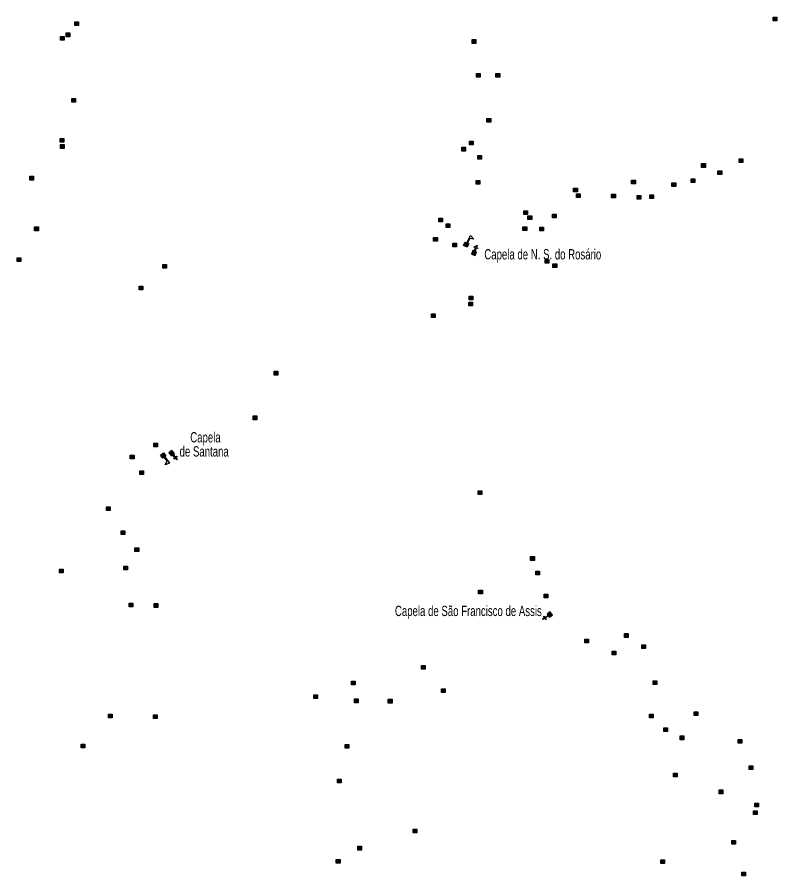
# Model space of a CAD drawing. Extents: x 649.2 to 674.4, y 7040 to 7068.1.
# Drawn here: x 662.26 to 668.19, y 7047.06 to 7053.75 of the extents above; entities that cross this region are included whole.
import ezdxf
from ezdxf.enums import TextEntityAlignment as Align

# ---------------------------------------------------------------- set-up
doc = ezdxf.new("R2010")
doc.units = 0
doc.header["$LTSCALE"] = 0.032
for name, color, linetype, lineweight in [('2', 7, 'Continuous', 25), ('4', 7, 'Continuous', 25), ('6', 7, 'Continuous', 25)]:
    doc.layers.add(name, color=color, linetype=linetype, lineweight=lineweight)
doc.layers.add('61', color=7, linetype='Continuous')

msp = doc.modelspace()

# ---------------------------------------------------------------- hatches: boundary and pattern name
at = {"layer": '2'}
for points in [[(668.1563, 7053.7499), (668.1853, 7053.7499), (668.1853, 7053.7209), (668.1563, 7053.7209)], [(662.7131, 7053.714), (662.7421, 7053.714), (662.7421, 7053.685), (662.7131, 7053.685)], [(662.6028, 7053.5993), (662.6318, 7053.5993), (662.6318, 7053.5703), (662.6028, 7053.5703)], [(662.645, 7053.6269), (662.674, 7053.6269), (662.674, 7053.5979), (662.645, 7053.5979)], [(665.811, 7053.5749), (665.84, 7053.5749), (665.84, 7053.5459), (665.811, 7053.5459)], [(665.8449, 7053.3102), (665.8739, 7053.3102), (665.8739, 7053.2812), (665.8449, 7053.2812)], [(665.9962, 7053.3115), (666.0252, 7053.3115), (666.0252, 7053.2825), (665.9962, 7053.2825)], [(662.6896, 7053.1161), (662.7186, 7053.1161), (662.7186, 7053.0871), (662.6896, 7053.0871)], [(665.9261, 7052.9598), (665.9551, 7052.9598), (665.9551, 7052.9308), (665.9261, 7052.9308)], [(662.5997, 7052.8044), (662.6287, 7052.8044), (662.6287, 7052.7754), (662.5997, 7052.7754)], [(662.6025, 7052.7567), (662.6315, 7052.7567), (662.6315, 7052.7277), (662.6025, 7052.7277)], [(665.7295, 7052.7358), (665.7585, 7052.7358), (665.7585, 7052.7068), (665.7295, 7052.7068)], [(665.7906, 7052.7828), (665.8196, 7052.7828), (665.8196, 7052.7538), (665.7906, 7052.7538)], [(665.8556, 7052.6727), (665.8846, 7052.6727), (665.8846, 7052.6437), (665.8556, 7052.6437)], [(667.5991, 7052.6086), (667.6281, 7052.6086), (667.6281, 7052.5796), (667.5991, 7052.5796)], [(667.8915, 7052.6472), (667.9205, 7052.6472), (667.9205, 7052.6182), (667.8915, 7052.6182)], [(667.7264, 7052.5524), (667.7554, 7052.5524), (667.7554, 7052.5234), (667.7264, 7052.5234)], [(662.3625, 7052.5097), (662.3915, 7052.5097), (662.3915, 7052.4807), (662.3625, 7052.4807)], [(665.8415, 7052.4779), (665.8705, 7052.4779), (665.8705, 7052.4489), (665.8415, 7052.4489)], [(667.0535, 7052.4799), (667.0825, 7052.4799), (667.0825, 7052.4509), (667.0535, 7052.4509)], [(667.3682, 7052.4585), (667.3972, 7052.4585), (667.3972, 7052.4295), (667.3682, 7052.4295)], [(667.5183, 7052.4909), (667.5473, 7052.4909), (667.5473, 7052.4619), (667.5183, 7052.4619)], [(666.6017, 7052.4172), (666.6307, 7052.4172), (666.6307, 7052.3882), (666.6017, 7052.3882)], [(666.6241, 7052.3725), (666.6531, 7052.3725), (666.6531, 7052.3435), (666.6241, 7052.3435)], [(666.8979, 7052.3717), (666.9269, 7052.3717), (666.9269, 7052.3427), (666.8979, 7052.3427)], [(667.0967, 7052.3615), (667.1257, 7052.3615), (667.1257, 7052.3325), (667.0967, 7052.3325)], [(667.1946, 7052.3651), (667.2236, 7052.3651), (667.2236, 7052.3361), (667.1946, 7052.3361)], [(666.2126, 7052.2412), (666.2416, 7052.2412), (666.2416, 7052.2122), (666.2126, 7052.2122)], [(666.2457, 7052.2023), (666.2747, 7052.2023), (666.2747, 7052.1733), (666.2457, 7052.1733)], [(666.4363, 7052.2149), (666.4653, 7052.2149), (666.4653, 7052.1859), (666.4363, 7052.1859)], [(665.5504, 7052.1842), (665.5794, 7052.1842), (665.5794, 7052.1552), (665.5504, 7052.1552)], [(665.6087, 7052.1395), (665.6377, 7052.1395), (665.6377, 7052.1105), (665.6087, 7052.1105)], [(662.4005, 7052.1151), (662.4295, 7052.1151), (662.4295, 7052.0861), (662.4005, 7052.0861)], [(666.2068, 7052.1157), (666.2358, 7052.1157), (666.2358, 7052.0867), (666.2068, 7052.0867)], [(666.3381, 7052.1147), (666.3671, 7052.1147), (666.3671, 7052.0857), (666.3381, 7052.0857)], [(665.5104, 7052.0332), (665.5394, 7052.0332), (665.5394, 7052.0042), (665.5104, 7052.0042)], [(665.6591, 7051.9884), (665.6881, 7051.9884), (665.6881, 7051.9594), (665.6591, 7051.9594)], [(662.2642, 7051.8752), (662.2932, 7051.8752), (662.2932, 7051.8462), (662.2642, 7051.8462)], [(666.3798, 7051.8613), (666.4088, 7051.8613), (666.4088, 7051.8323), (666.3798, 7051.8323)], [(663.3997, 7051.8231), (663.4287, 7051.8231), (663.4287, 7051.7941), (663.3997, 7051.7941)], [(666.4403, 7051.829), (666.4693, 7051.829), (666.4693, 7051.8), (666.4403, 7051.8)], [(663.2147, 7051.6548), (663.2437, 7051.6548), (663.2437, 7051.6258), (663.2147, 7051.6258)], [(665.7852, 7051.5282), (665.8142, 7051.5282), (665.8142, 7051.4992), (665.7852, 7051.4992)], [(665.7871, 7051.5751), (665.8161, 7051.5751), (665.8161, 7051.5461), (665.7871, 7051.5461)], [(665.4924, 7051.4392), (665.5214, 7051.4392), (665.5214, 7051.4102), (665.4924, 7051.4102)], [(664.267, 7050.9904), (664.296, 7050.9904), (664.296, 7050.9614), (664.267, 7050.9614)], [(664.1026, 7050.6421), (664.1316, 7050.6421), (664.1316, 7050.6131), (664.1026, 7050.6131)], [(663.3297, 7050.431), (663.3587, 7050.431), (663.3587, 7050.402), (663.3297, 7050.402)], [(663.146, 7050.3366), (663.175, 7050.3366), (663.175, 7050.3076), (663.146, 7050.3076)], [(663.2206, 7050.2153), (663.2496, 7050.2153), (663.2496, 7050.1863), (663.2206, 7050.1863)], [(665.8575, 7050.0582), (665.8865, 7050.0582), (665.8865, 7050.0292), (665.8575, 7050.0292)], [(662.9598, 7049.9353), (662.9888, 7049.9353), (662.9888, 7049.9063), (662.9598, 7049.9063)], [(663.0741, 7049.7483), (663.1031, 7049.7483), (663.1031, 7049.7193), (663.0741, 7049.7193)], [(663.1824, 7049.6147), (663.2114, 7049.6147), (663.2114, 7049.5857), (663.1824, 7049.5857)], [(666.2664, 7049.5462), (666.2954, 7049.5462), (666.2954, 7049.5172), (666.2664, 7049.5172)], [(662.5947, 7049.4484), (662.6237, 7049.4484), (662.6237, 7049.4194), (662.5947, 7049.4194)], [(663.0949, 7049.4722), (663.1239, 7049.4722), (663.1239, 7049.4432), (663.0949, 7049.4432)], [(666.3071, 7049.4324), (666.3361, 7049.4324), (666.3361, 7049.4034), (666.3071, 7049.4034)], [(665.861, 7049.286), (665.89, 7049.286), (665.89, 7049.257), (665.861, 7049.257)], [(666.3711, 7049.2535), (666.4001, 7049.2535), (666.4001, 7049.2245), (666.3711, 7049.2245)], [(663.1364, 7049.1828), (663.1654, 7049.1828), (663.1654, 7049.1538), (663.1364, 7049.1538)], [(663.3324, 7049.1798), (663.3614, 7049.1798), (663.3614, 7049.1508), (663.3324, 7049.1508)], [(666.9973, 7048.946), (667.0263, 7048.946), (667.0263, 7048.917), (666.9973, 7048.917)], [(666.6883, 7048.9031), (666.7173, 7048.9031), (666.7173, 7048.8741), (666.6883, 7048.8741)], [(667.1336, 7048.8593), (667.1626, 7048.8593), (667.1626, 7048.8303), (667.1336, 7048.8303)], [(666.9023, 7048.8097), (666.9313, 7048.8097), (666.9313, 7048.7807), (666.9023, 7048.7807)], [(665.4155, 7048.6974), (665.4445, 7048.6974), (665.4445, 7048.6684), (665.4155, 7048.6684)], [(667.2212, 7048.5782), (667.2502, 7048.5782), (667.2502, 7048.5492), (667.2212, 7048.5492)], [(664.869, 7048.5753), (664.898, 7048.5753), (664.898, 7048.5463), (664.869, 7048.5463)], [(665.5709, 7048.5156), (665.5999, 7048.5156), (665.5999, 7048.4866), (665.5709, 7048.4866)], [(664.5755, 7048.4699), (664.6045, 7048.4699), (664.6045, 7048.4409), (664.5755, 7048.4409)], [(664.8937, 7048.437), (664.9227, 7048.437), (664.9227, 7048.408), (664.8937, 7048.408)], [(665.157, 7048.4341), (665.186, 7048.4341), (665.186, 7048.4051), (665.157, 7048.4051)], [(662.9751, 7048.319), (663.0041, 7048.319), (663.0041, 7048.29), (662.9751, 7048.29)], [(663.3259, 7048.3145), (663.3549, 7048.3145), (663.3549, 7048.2855), (663.3259, 7048.2855)], [(667.1921, 7048.319), (667.2211, 7048.319), (667.2211, 7048.29), (667.1921, 7048.29)], [(667.5412, 7048.3375), (667.5702, 7048.3375), (667.5702, 7048.3085), (667.5412, 7048.3085)], [(667.3045, 7048.2132), (667.3335, 7048.2132), (667.3335, 7048.1842), (667.3045, 7048.1842)], [(667.4314, 7048.1484), (667.4604, 7048.1484), (667.4604, 7048.1194), (667.4314, 7048.1194)], [(667.8838, 7048.1206), (667.9128, 7048.1206), (667.9128, 7048.0916), (667.8838, 7048.0916)], [(662.7631, 7048.0845), (662.7921, 7048.0845), (662.7921, 7048.0555), (662.7631, 7048.0555)], [(664.8205, 7048.0823), (664.8495, 7048.0823), (664.8495, 7048.0533), (664.8205, 7048.0533)], [(667.9692, 7047.9162), (667.9982, 7047.9162), (667.9982, 7047.8872), (667.9692, 7047.8872)], [(667.3801, 7047.8582), (667.4091, 7047.8582), (667.4091, 7047.8292), (667.3801, 7047.8292)], [(664.7604, 7047.8114), (664.7894, 7047.8114), (664.7894, 7047.7824), (664.7604, 7047.7824)], [(667.735, 7047.7279), (667.764, 7047.7279), (667.764, 7047.6989), (667.735, 7047.6989)], [(668.0138, 7047.6241), (668.0428, 7047.6241), (668.0428, 7047.5951), (668.0138, 7047.5951)], [(668.0042, 7047.5649), (668.0332, 7047.5649), (668.0332, 7047.5359), (668.0042, 7047.5359)], [(665.3506, 7047.4223), (665.3796, 7047.4223), (665.3796, 7047.3933), (665.3506, 7047.3933)], [(667.8344, 7047.335), (667.8634, 7047.335), (667.8634, 7047.306), (667.8344, 7047.306)], [(664.9203, 7047.2888), (664.9493, 7047.2888), (664.9493, 7047.2598), (664.9203, 7047.2598)], [(664.7517, 7047.1857), (664.7807, 7047.1857), (664.7807, 7047.1567), (664.7517, 7047.1567)], [(667.2809, 7047.1826), (667.3099, 7047.1826), (667.3099, 7047.1536), (667.2809, 7047.1536)], [(667.9123, 7047.0877), (667.9413, 7047.0877), (667.9413, 7047.0587), (667.9123, 7047.0587)]]:
    msp.add_hatch(color=256, dxfattribs=at).paths.add_polyline_path(points)
at = {"layer": '4'}
for points in [[(665.7441, 7051.9711), (665.7578, 7051.9977), (665.7845, 7051.984), (665.7708, 7051.9573)], [(663.4059, 7050.3545), (663.4242, 7050.3308), (663.4004, 7050.3125), (663.3821, 7050.3362)]]:
    msp.add_hatch(color=256, dxfattribs=at).paths.add_polyline_path(points)
at = {"layer": '6'}
for points in [[(665.8158, 7051.9312), (665.8051, 7051.9032), (665.8331, 7051.8925), (665.8438, 7051.9205)], [(665.8321, 7051.925), (665.8275, 7051.9267), (665.8373, 7051.9524), (665.8256, 7051.9569), (665.8273, 7051.9616), (665.839, 7051.9571), (665.8453, 7051.9735), (665.8499, 7051.9717), (665.8437, 7051.9553), (665.8554, 7051.9509), (665.8536, 7051.9462), (665.8419, 7051.9507)], [(663.4893, 7050.3505), (663.47, 7050.3734), (663.4471, 7050.354), (663.4664, 7050.3311)], [(663.476, 7050.3392), (663.4798, 7050.3424), (663.4975, 7050.3214), (663.5071, 7050.3295), (663.5103, 7050.3256), (663.5007, 7050.3176), (663.512, 7050.3042), (663.5082, 7050.301), (663.4969, 7050.3143), (663.4874, 7050.3063), (663.4841, 7050.3101), (663.4937, 7050.3182)], [(666.4112, 7049.074), (666.4359, 7049.0909), (666.4191, 7049.1157), (666.3943, 7049.0988)], [(666.4013, 7049.0885), (666.4041, 7049.0843), (666.3814, 7049.0688), (666.3884, 7049.0585), (666.3843, 7049.0557), (666.3773, 7049.066), (666.3628, 7049.0562), (666.36, 7049.0603), (666.3744, 7049.0702), (666.3674, 7049.0805), (666.3715, 7049.0833), (666.3786, 7049.073)]]:
    msp.add_hatch(color=256, dxfattribs=at).paths.add_polyline_path(points)

# ---------------------------------------------------------------- linework, layer by layer
at = {"layer": '2'}
for points in [[(668.1563, 7053.7499), (668.1853, 7053.7499), (668.1853, 7053.7209), (668.1563, 7053.7209)], [(662.7131, 7053.714), (662.7421, 7053.714), (662.7421, 7053.685), (662.7131, 7053.685)], [(662.6028, 7053.5993), (662.6318, 7053.5993), (662.6318, 7053.5703), (662.6028, 7053.5703)], [(662.645, 7053.6269), (662.674, 7053.6269), (662.674, 7053.5979), (662.645, 7053.5979)], [(665.811, 7053.5749), (665.84, 7053.5749), (665.84, 7053.5459), (665.811, 7053.5459)], [(665.8449, 7053.3102), (665.8739, 7053.3102), (665.8739, 7053.2812), (665.8449, 7053.2812)], [(665.9962, 7053.3115), (666.0252, 7053.3115), (666.0252, 7053.2825), (665.9962, 7053.2825)], [(662.6896, 7053.1161), (662.7186, 7053.1161), (662.7186, 7053.0871), (662.6896, 7053.0871)], [(665.9261, 7052.9598), (665.9551, 7052.9598), (665.9551, 7052.9308), (665.9261, 7052.9308)], [(662.5997, 7052.8044), (662.6287, 7052.8044), (662.6287, 7052.7754), (662.5997, 7052.7754)], [(662.6025, 7052.7567), (662.6315, 7052.7567), (662.6315, 7052.7277), (662.6025, 7052.7277)], [(665.7295, 7052.7358), (665.7585, 7052.7358), (665.7585, 7052.7068), (665.7295, 7052.7068)], [(665.7906, 7052.7828), (665.8196, 7052.7828), (665.8196, 7052.7538), (665.7906, 7052.7538)], [(665.8556, 7052.6727), (665.8846, 7052.6727), (665.8846, 7052.6437), (665.8556, 7052.6437)], [(667.5991, 7052.6086), (667.6281, 7052.6086), (667.6281, 7052.5796), (667.5991, 7052.5796)], [(667.8915, 7052.6472), (667.9205, 7052.6472), (667.9205, 7052.6182), (667.8915, 7052.6182)], [(667.7264, 7052.5524), (667.7554, 7052.5524), (667.7554, 7052.5234), (667.7264, 7052.5234)], [(662.3625, 7052.5097), (662.3915, 7052.5097), (662.3915, 7052.4807), (662.3625, 7052.4807)], [(665.8415, 7052.4779), (665.8705, 7052.4779), (665.8705, 7052.4489), (665.8415, 7052.4489)], [(667.0535, 7052.4799), (667.0825, 7052.4799), (667.0825, 7052.4509), (667.0535, 7052.4509)], [(667.3682, 7052.4585), (667.3972, 7052.4585), (667.3972, 7052.4295), (667.3682, 7052.4295)], [(667.5183, 7052.4909), (667.5473, 7052.4909), (667.5473, 7052.4619), (667.5183, 7052.4619)], [(666.6017, 7052.4172), (666.6307, 7052.4172), (666.6307, 7052.3882), (666.6017, 7052.3882)], [(666.6241, 7052.3725), (666.6531, 7052.3725), (666.6531, 7052.3435), (666.6241, 7052.3435)], [(666.8979, 7052.3717), (666.9269, 7052.3717), (666.9269, 7052.3427), (666.8979, 7052.3427)], [(667.0967, 7052.3615), (667.1257, 7052.3615), (667.1257, 7052.3325), (667.0967, 7052.3325)], [(667.1946, 7052.3651), (667.2236, 7052.3651), (667.2236, 7052.3361), (667.1946, 7052.3361)], [(666.2126, 7052.2412), (666.2416, 7052.2412), (666.2416, 7052.2122), (666.2126, 7052.2122)], [(666.2457, 7052.2023), (666.2747, 7052.2023), (666.2747, 7052.1733), (666.2457, 7052.1733)], [(666.4363, 7052.2149), (666.4653, 7052.2149), (666.4653, 7052.1859), (666.4363, 7052.1859)], [(665.5504, 7052.1842), (665.5794, 7052.1842), (665.5794, 7052.1552), (665.5504, 7052.1552)], [(665.6087, 7052.1395), (665.6377, 7052.1395), (665.6377, 7052.1105), (665.6087, 7052.1105)], [(662.4005, 7052.1151), (662.4295, 7052.1151), (662.4295, 7052.0861), (662.4005, 7052.0861)], [(666.2068, 7052.1157), (666.2358, 7052.1157), (666.2358, 7052.0867), (666.2068, 7052.0867)], [(666.3381, 7052.1147), (666.3671, 7052.1147), (666.3671, 7052.0857), (666.3381, 7052.0857)], [(665.5104, 7052.0332), (665.5394, 7052.0332), (665.5394, 7052.0042), (665.5104, 7052.0042)], [(665.6591, 7051.9884), (665.6881, 7051.9884), (665.6881, 7051.9594), (665.6591, 7051.9594)], [(662.2642, 7051.8752), (662.2932, 7051.8752), (662.2932, 7051.8462), (662.2642, 7051.8462)], [(666.3798, 7051.8613), (666.4088, 7051.8613), (666.4088, 7051.8323), (666.3798, 7051.8323)], [(663.3997, 7051.8231), (663.4287, 7051.8231), (663.4287, 7051.7941), (663.3997, 7051.7941)], [(666.4403, 7051.829), (666.4693, 7051.829), (666.4693, 7051.8), (666.4403, 7051.8)], [(663.2147, 7051.6548), (663.2437, 7051.6548), (663.2437, 7051.6258), (663.2147, 7051.6258)], [(665.7852, 7051.5282), (665.8142, 7051.5282), (665.8142, 7051.4992), (665.7852, 7051.4992)], [(665.7871, 7051.5751), (665.8161, 7051.5751), (665.8161, 7051.5461), (665.7871, 7051.5461)], [(665.4924, 7051.4392), (665.5214, 7051.4392), (665.5214, 7051.4102), (665.4924, 7051.4102)], [(664.267, 7050.9904), (664.296, 7050.9904), (664.296, 7050.9614), (664.267, 7050.9614)], [(664.1026, 7050.6421), (664.1316, 7050.6421), (664.1316, 7050.6131), (664.1026, 7050.6131)], [(663.3297, 7050.431), (663.3587, 7050.431), (663.3587, 7050.402), (663.3297, 7050.402)], [(663.146, 7050.3366), (663.175, 7050.3366), (663.175, 7050.3076), (663.146, 7050.3076)], [(663.2206, 7050.2153), (663.2496, 7050.2153), (663.2496, 7050.1863), (663.2206, 7050.1863)], [(665.8575, 7050.0582), (665.8865, 7050.0582), (665.8865, 7050.0292), (665.8575, 7050.0292)], [(662.9598, 7049.9353), (662.9888, 7049.9353), (662.9888, 7049.9063), (662.9598, 7049.9063)], [(663.0741, 7049.7483), (663.1031, 7049.7483), (663.1031, 7049.7193), (663.0741, 7049.7193)], [(663.1824, 7049.6147), (663.2114, 7049.6147), (663.2114, 7049.5857), (663.1824, 7049.5857)], [(666.2664, 7049.5462), (666.2954, 7049.5462), (666.2954, 7049.5172), (666.2664, 7049.5172)], [(662.5947, 7049.4484), (662.6237, 7049.4484), (662.6237, 7049.4194), (662.5947, 7049.4194)], [(663.0949, 7049.4722), (663.1239, 7049.4722), (663.1239, 7049.4432), (663.0949, 7049.4432)], [(666.3071, 7049.4324), (666.3361, 7049.4324), (666.3361, 7049.4034), (666.3071, 7049.4034)], [(665.861, 7049.286), (665.89, 7049.286), (665.89, 7049.257), (665.861, 7049.257)], [(666.3711, 7049.2535), (666.4001, 7049.2535), (666.4001, 7049.2245), (666.3711, 7049.2245)], [(663.1364, 7049.1828), (663.1654, 7049.1828), (663.1654, 7049.1538), (663.1364, 7049.1538)], [(663.3324, 7049.1798), (663.3614, 7049.1798), (663.3614, 7049.1508), (663.3324, 7049.1508)], [(666.9973, 7048.946), (667.0263, 7048.946), (667.0263, 7048.917), (666.9973, 7048.917)], [(666.6883, 7048.9031), (666.7173, 7048.9031), (666.7173, 7048.8741), (666.6883, 7048.8741)], [(667.1336, 7048.8593), (667.1626, 7048.8593), (667.1626, 7048.8303), (667.1336, 7048.8303)], [(666.9023, 7048.8097), (666.9313, 7048.8097), (666.9313, 7048.7807), (666.9023, 7048.7807)], [(665.4155, 7048.6974), (665.4445, 7048.6974), (665.4445, 7048.6684), (665.4155, 7048.6684)], [(667.2212, 7048.5782), (667.2502, 7048.5782), (667.2502, 7048.5492), (667.2212, 7048.5492)], [(664.869, 7048.5753), (664.898, 7048.5753), (664.898, 7048.5463), (664.869, 7048.5463)], [(665.5709, 7048.5156), (665.5999, 7048.5156), (665.5999, 7048.4866), (665.5709, 7048.4866)], [(664.5755, 7048.4699), (664.6045, 7048.4699), (664.6045, 7048.4409), (664.5755, 7048.4409)], [(664.8937, 7048.437), (664.9227, 7048.437), (664.9227, 7048.408), (664.8937, 7048.408)], [(665.157, 7048.4341), (665.186, 7048.4341), (665.186, 7048.4051), (665.157, 7048.4051)], [(662.9751, 7048.319), (663.0041, 7048.319), (663.0041, 7048.29), (662.9751, 7048.29)], [(663.3259, 7048.3145), (663.3549, 7048.3145), (663.3549, 7048.2855), (663.3259, 7048.2855)], [(667.1921, 7048.319), (667.2211, 7048.319), (667.2211, 7048.29), (667.1921, 7048.29)], [(667.5412, 7048.3375), (667.5702, 7048.3375), (667.5702, 7048.3085), (667.5412, 7048.3085)], [(667.3045, 7048.2132), (667.3335, 7048.2132), (667.3335, 7048.1842), (667.3045, 7048.1842)], [(667.4314, 7048.1484), (667.4604, 7048.1484), (667.4604, 7048.1194), (667.4314, 7048.1194)], [(667.8838, 7048.1206), (667.9128, 7048.1206), (667.9128, 7048.0916), (667.8838, 7048.0916)], [(662.7631, 7048.0845), (662.7921, 7048.0845), (662.7921, 7048.0555), (662.7631, 7048.0555)], [(664.8205, 7048.0823), (664.8495, 7048.0823), (664.8495, 7048.0533), (664.8205, 7048.0533)], [(667.9692, 7047.9162), (667.9982, 7047.9162), (667.9982, 7047.8872), (667.9692, 7047.8872)], [(667.3801, 7047.8582), (667.4091, 7047.8582), (667.4091, 7047.8292), (667.3801, 7047.8292)], [(664.7604, 7047.8114), (664.7894, 7047.8114), (664.7894, 7047.7824), (664.7604, 7047.7824)], [(667.735, 7047.7279), (667.764, 7047.7279), (667.764, 7047.6989), (667.735, 7047.6989)], [(668.0138, 7047.6241), (668.0428, 7047.6241), (668.0428, 7047.5951), (668.0138, 7047.5951)], [(668.0042, 7047.5649), (668.0332, 7047.5649), (668.0332, 7047.5359), (668.0042, 7047.5359)], [(665.3506, 7047.4223), (665.3796, 7047.4223), (665.3796, 7047.3933), (665.3506, 7047.3933)], [(667.8344, 7047.335), (667.8634, 7047.335), (667.8634, 7047.306), (667.8344, 7047.306)], [(664.9203, 7047.2888), (664.9493, 7047.2888), (664.9493, 7047.2598), (664.9203, 7047.2598)], [(664.7517, 7047.1857), (664.7807, 7047.1857), (664.7807, 7047.1567), (664.7517, 7047.1567)], [(667.2809, 7047.1826), (667.3099, 7047.1826), (667.3099, 7047.1536), (667.2809, 7047.1536)], [(667.9123, 7047.0877), (667.9413, 7047.0877), (667.9413, 7047.0587), (667.9123, 7047.0587)]]:
    msp.add_lwpolyline(points, close=True, dxfattribs=at)
at = {"layer": '4'}
for p, q in [((665.7689, 7051.992), (665.7734, 7051.9897)), ((663.4143, 7050.3232), (663.4103, 7050.3201))]:
    msp.add_line(p, q, dxfattribs=at)
for points in [[(665.7441, 7051.9711), (665.7578, 7051.9977), (665.7845, 7051.984), (665.7708, 7051.9573)], [(665.7689, 7051.992), (665.7975, 7052.0476), (665.8229, 7052.0205), (665.7914, 7052.0249), (665.7734, 7051.9897)], [(663.4059, 7050.3545), (663.4242, 7050.3308), (663.4004, 7050.3125), (663.3821, 7050.3362)], [(663.4143, 7050.3232), (663.4524, 7050.2736), (663.4171, 7050.2622), (663.4344, 7050.2888), (663.4103, 7050.3201)]]:
    msp.add_lwpolyline(points, close=True, dxfattribs=at)
at = {"layer": '6'}
for points in [[(665.8158, 7051.9312), (665.8051, 7051.9032), (665.8331, 7051.8925), (665.8438, 7051.9205)], [(665.8321, 7051.925), (665.8275, 7051.9267), (665.8373, 7051.9524), (665.8256, 7051.9569), (665.8273, 7051.9616), (665.839, 7051.9571), (665.8453, 7051.9735), (665.8499, 7051.9717), (665.8437, 7051.9553), (665.8554, 7051.9509), (665.8536, 7051.9462), (665.8419, 7051.9507)], [(663.4893, 7050.3505), (663.47, 7050.3734), (663.4471, 7050.354), (663.4664, 7050.3311)], [(663.476, 7050.3392), (663.4798, 7050.3424), (663.4975, 7050.3214), (663.5071, 7050.3295), (663.5103, 7050.3256), (663.5007, 7050.3176), (663.512, 7050.3042), (663.5082, 7050.301), (663.4969, 7050.3143), (663.4874, 7050.3063), (663.4841, 7050.3101), (663.4937, 7050.3182)], [(666.4112, 7049.074), (666.4359, 7049.0909), (666.4191, 7049.1157), (666.3943, 7049.0988)], [(666.4013, 7049.0885), (666.4041, 7049.0843), (666.3814, 7049.0688), (666.3884, 7049.0585), (666.3843, 7049.0557), (666.3773, 7049.066), (666.3628, 7049.0562), (666.36, 7049.0603), (666.3744, 7049.0702), (666.3674, 7049.0805), (666.3715, 7049.0833), (666.3786, 7049.073)]]:
    msp.add_lwpolyline(points, close=True, dxfattribs=at)

# ---------------------------------------------------------------- texts
at = {"layer": '61', "width": 0.7}
for s, p in [('Capela de N. S. do Rosário', (665.9054, 7051.8621)), ('    Capela', (663.5301, 7050.4362)), ('de Santana', (663.5301, 7050.3262))]:
    msp.add_text(s, height=0.08, dxfattribs=at).set_placement(p)
msp.add_text('Capela de São Francisco de Assis', height=0.08, dxfattribs=at).set_placement((666.3534, 7049.083), align=Align.RIGHT)

doc.saveas('drawing.dxf')
